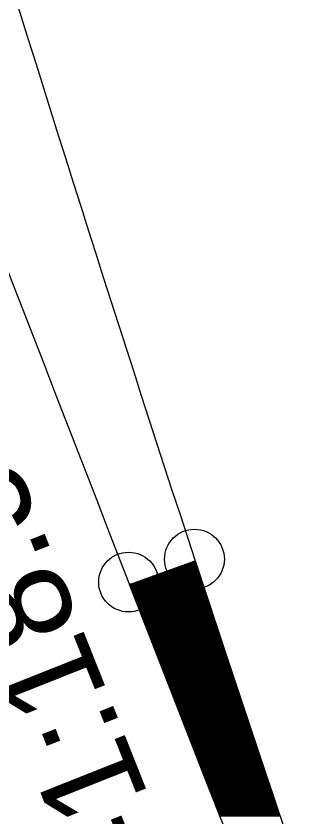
# Model space of a CAD drawing. Extents: x 149855 to 151460, y 6580726 to 6583068.
# Drawn here: x 151017.81 to 151025.23, y 6581493.39 to 6581513.46 of the extents above; entities that cross this region are included whole.
import ezdxf

# ---------------------------------------------------------------- set-up
doc = ezdxf.new("R2010")
doc.units = 0
for name, color, linetype in [('Spårmitt L', 7, 'Continuous'), ('Tp bef behålls P', 7, 'Continuous'), ('Växel L', 7, 'Continuous'), ('Växeltyp T', 7, 'Continuous')]:
    doc.layers.add(name, color=color, linetype=linetype)

msp = doc.modelspace()

# ---------------------------------------------------------------- linework, layer by layer
at = {"layer": 'Spårmitt L'}
for centre, radius, start, end in [((151635.017, 6581718.794), 629.5, 193.95613, 203.78913), ((154375.793, 6582804.201), 3600, 200.503925, 201.252844), ((151878.454, 6581780.709), 901.064, 195.629249, 198.165417), ((154379.055, 6582805.47), 3603.5, 201.252844, 202.283548)]:
    msp.add_arc(centre, radius, start, end, dxfattribs=at)
at = {"layer": 'Tp bef behålls P'}
for centre in [(151022.281, 6581499.835), (151020.63, 6581499.258)]:
    msp.add_circle(centre, 0.75, dxfattribs=at)
at = {"layer": 'Växel L'}
for p, q in [((151022.188, 6581499.752), (151022.312, 6581499.752)), ((151022.244, 6581499.772), (151022.306, 6581499.772)), ((151021.63, 6581499.552), (151022.378, 6581499.552)), ((151021.686, 6581499.572), (151022.372, 6581499.572)), ((151021.741, 6581499.592), (151022.365, 6581499.592)), ((151021.797, 6581499.612), (151022.358, 6581499.612)), ((151021.853, 6581499.632), (151022.352, 6581499.632)), ((151021.909, 6581499.652), (151022.345, 6581499.652)), ((151021.965, 6581499.672), (151022.339, 6581499.672)), ((151022.021, 6581499.692), (151022.332, 6581499.692)), ((151022.076, 6581499.712), (151022.325, 6581499.712)), ((151022.132, 6581499.732), (151022.319, 6581499.732)), ((151021.071, 6581499.352), (151022.444, 6581499.352)), ((151021.127, 6581499.372), (151022.437, 6581499.372)), ((151021.183, 6581499.392), (151022.431, 6581499.392)), ((151021.239, 6581499.412), (151022.424, 6581499.412)), ((151021.295, 6581499.432), (151022.418, 6581499.432)), ((151021.351, 6581499.452), (151022.411, 6581499.452)), ((151021.406, 6581499.472), (151022.404, 6581499.472)), ((151021.462, 6581499.492), (151022.398, 6581499.492)), ((151021.518, 6581499.512), (151022.391, 6581499.512)), ((151021.574, 6581499.532), (151022.385, 6581499.532)), ((151020.655, 6581499.192), (151022.497, 6581499.192)), ((151020.663, 6581499.172), (151022.503, 6581499.172)), ((151020.671, 6581499.152), (151022.51, 6581499.152)), ((151020.681, 6581499.212), (151022.49, 6581499.212)), ((151020.736, 6581499.232), (151022.484, 6581499.232)), ((151020.792, 6581499.252), (151022.477, 6581499.252)), ((151020.848, 6581499.272), (151022.47, 6581499.272)), ((151020.904, 6581499.292), (151022.464, 6581499.292)), ((151020.96, 6581499.312), (151022.457, 6581499.312)), ((151021.016, 6581499.332), (151022.451, 6581499.332)), ((151020.679, 6581499.132), (151022.517, 6581499.132)), ((151020.687, 6581499.112), (151022.523, 6581499.112)), ((151020.694, 6581499.092), (151022.53, 6581499.092)), ((151020.702, 6581499.072), (151022.536, 6581499.072)), ((151020.71, 6581499.052), (151022.543, 6581499.052)), ((151020.718, 6581499.032), (151022.55, 6581499.032)), ((151020.726, 6581499.012), (151022.556, 6581499.012)), ((151020.733, 6581498.992), (151022.563, 6581498.992)), ((151020.741, 6581498.972), (151022.569, 6581498.972)), ((151020.749, 6581498.952), (151022.576, 6581498.952)), ((151020.757, 6581498.932), (151022.582, 6581498.932)), ((151020.765, 6581498.912), (151022.589, 6581498.912)), ((151020.772, 6581498.892), (151022.596, 6581498.892)), ((151020.78, 6581498.872), (151022.602, 6581498.872)), ((151020.788, 6581498.852), (151022.609, 6581498.852)), ((151020.796, 6581498.832), (151022.615, 6581498.832)), ((151020.804, 6581498.812), (151022.622, 6581498.812)), ((151020.811, 6581498.792), (151022.629, 6581498.792)), ((151020.819, 6581498.772), (151022.635, 6581498.772)), ((151020.827, 6581498.752), (151022.642, 6581498.752)), ((151020.835, 6581498.732), (151022.648, 6581498.732)), ((151020.843, 6581498.712), (151022.655, 6581498.712)), ((151020.85, 6581498.692), (151022.662, 6581498.692)), ((151020.858, 6581498.672), (151022.668, 6581498.672)), ((151020.866, 6581498.652), (151022.675, 6581498.652)), ((151020.874, 6581498.632), (151022.681, 6581498.632)), ((151020.882, 6581498.612), (151022.688, 6581498.612)), ((151020.889, 6581498.592), (151022.695, 6581498.592)), ((151020.897, 6581498.572), (151022.701, 6581498.572)), ((151020.905, 6581498.552), (151022.708, 6581498.552)), ((151020.913, 6581498.532), (151022.714, 6581498.532)), ((151020.92, 6581498.512), (151022.721, 6581498.512)), ((151020.928, 6581498.492), (151022.728, 6581498.492)), ((151020.936, 6581498.472), (151022.734, 6581498.472)), ((151020.944, 6581498.452), (151022.741, 6581498.452)), ((151020.952, 6581498.432), (151022.747, 6581498.432)), ((151020.959, 6581498.412), (151022.754, 6581498.412)), ((151020.967, 6581498.392), (151022.761, 6581498.392)), ((151020.975, 6581498.372), (151022.767, 6581498.372)), ((151020.983, 6581498.352), (151022.774, 6581498.352)), ((151020.991, 6581498.332), (151022.78, 6581498.332)), ((151020.998, 6581498.312), (151022.787, 6581498.312)), ((151021.006, 6581498.292), (151022.793, 6581498.292)), ((151021.014, 6581498.272), (151022.8, 6581498.272)), ((151021.022, 6581498.252), (151022.807, 6581498.252)), ((151021.03, 6581498.232), (151022.813, 6581498.232)), ((151021.037, 6581498.212), (151022.82, 6581498.212)), ((151021.045, 6581498.192), (151022.826, 6581498.192)), ((151021.053, 6581498.172), (151022.833, 6581498.172)), ((151021.061, 6581498.152), (151022.84, 6581498.152)), ((151021.069, 6581498.132), (151022.846, 6581498.132)), ((151021.076, 6581498.112), (151022.853, 6581498.112)), ((151021.084, 6581498.092), (151022.859, 6581498.092)), ((151021.092, 6581498.072), (151022.866, 6581498.072)), ((151021.1, 6581498.052), (151022.873, 6581498.052)), ((151021.108, 6581498.032), (151022.879, 6581498.032)), ((151021.115, 6581498.012), (151022.886, 6581498.012)), ((151021.123, 6581497.992), (151022.892, 6581497.992)), ((151021.131, 6581497.972), (151022.899, 6581497.972)), ((151021.139, 6581497.952), (151022.906, 6581497.952)), ((151021.147, 6581497.932), (151022.912, 6581497.932)), ((151021.154, 6581497.912), (151022.919, 6581497.912)), ((151021.162, 6581497.892), (151022.925, 6581497.892)), ((151021.17, 6581497.872), (151022.932, 6581497.872)), ((151021.178, 6581497.852), (151022.939, 6581497.852)), ((151021.186, 6581497.832), (151022.945, 6581497.832)), ((151021.193, 6581497.812), (151022.952, 6581497.812)), ((151021.201, 6581497.792), (151022.958, 6581497.792)), ((151021.209, 6581497.772), (151022.965, 6581497.772)), ((151021.217, 6581497.752), (151022.972, 6581497.752)), ((151021.225, 6581497.732), (151022.978, 6581497.732)), ((151021.232, 6581497.712), (151022.985, 6581497.712)), ((151021.24, 6581497.692), (151022.991, 6581497.692)), ((151021.248, 6581497.672), (151022.998, 6581497.672)), ((151021.256, 6581497.652), (151023.004, 6581497.652)), ((151021.264, 6581497.632), (151023.011, 6581497.632)), ((151021.271, 6581497.612), (151023.018, 6581497.612)), ((151021.279, 6581497.592), (151023.024, 6581497.592)), ((151021.287, 6581497.572), (151023.031, 6581497.572)), ((151021.295, 6581497.552), (151023.037, 6581497.552)), ((151021.302, 6581497.532), (151023.044, 6581497.532)), ((151021.31, 6581497.512), (151023.051, 6581497.512)), ((151021.318, 6581497.492), (151023.057, 6581497.492)), ((151021.326, 6581497.472), (151023.064, 6581497.472)), ((151021.334, 6581497.452), (151023.07, 6581497.452)), ((151021.341, 6581497.432), (151023.077, 6581497.432)), ((151021.349, 6581497.412), (151023.084, 6581497.412)), ((151021.357, 6581497.392), (151023.09, 6581497.392)), ((151021.365, 6581497.372), (151023.097, 6581497.372)), ((151021.373, 6581497.352), (151023.103, 6581497.352)), ((151021.38, 6581497.332), (151023.11, 6581497.332)), ((151021.388, 6581497.312), (151023.117, 6581497.312)), ((151021.396, 6581497.292), (151023.123, 6581497.292)), ((151021.404, 6581497.272), (151023.13, 6581497.272)), ((151021.412, 6581497.252), (151023.136, 6581497.252)), ((151021.419, 6581497.232), (151023.143, 6581497.232)), ((151021.427, 6581497.212), (151023.15, 6581497.212)), ((151021.435, 6581497.192), (151023.156, 6581497.192)), ((151021.443, 6581497.172), (151023.163, 6581497.172)), ((151021.451, 6581497.152), (151023.17, 6581497.152)), ((151021.458, 6581497.132), (151023.176, 6581497.132)), ((151021.466, 6581497.112), (151023.183, 6581497.112)), ((151021.474, 6581497.092), (151023.19, 6581497.092)), ((151021.482, 6581497.072), (151023.196, 6581497.072)), ((151021.49, 6581497.052), (151023.203, 6581497.052)), ((151021.497, 6581497.032), (151023.21, 6581497.032)), ((151021.505, 6581497.012), (151023.216, 6581497.012)), ((151021.513, 6581496.992), (151023.223, 6581496.992)), ((151021.521, 6581496.972), (151023.23, 6581496.972)), ((151021.529, 6581496.952), (151023.236, 6581496.952)), ((151021.536, 6581496.932), (151023.243, 6581496.932)), ((151021.544, 6581496.912), (151023.249, 6581496.912)), ((151021.552, 6581496.892), (151023.256, 6581496.892)), ((151021.56, 6581496.872), (151023.263, 6581496.872)), ((151021.568, 6581496.852), (151023.269, 6581496.852)), ((151021.575, 6581496.832), (151023.276, 6581496.832)), ((151021.583, 6581496.812), (151023.283, 6581496.812)), ((151021.591, 6581496.792), (151023.289, 6581496.792)), ((151021.599, 6581496.772), (151023.296, 6581496.772)), ((151021.607, 6581496.752), (151023.303, 6581496.752)), ((151021.614, 6581496.732), (151023.309, 6581496.732)), ((151021.622, 6581496.712), (151023.316, 6581496.712)), ((151021.63, 6581496.692), (151023.323, 6581496.692)), ((151021.638, 6581496.672), (151023.329, 6581496.672)), ((151021.646, 6581496.652), (151023.336, 6581496.652)), ((151021.653, 6581496.632), (151023.343, 6581496.632)), ((151021.661, 6581496.612), (151023.349, 6581496.612)), ((151021.669, 6581496.592), (151023.356, 6581496.592)), ((151021.677, 6581496.572), (151023.363, 6581496.572)), ((151021.685, 6581496.552), (151023.369, 6581496.552)), ((151021.692, 6581496.532), (151023.376, 6581496.532)), ((151021.7, 6581496.512), (151023.383, 6581496.512)), ((151021.708, 6581496.492), (151023.389, 6581496.492)), ((151021.716, 6581496.472), (151023.396, 6581496.472)), ((151021.723, 6581496.452), (151023.403, 6581496.452)), ((151021.731, 6581496.432), (151023.409, 6581496.432)), ((151021.739, 6581496.412), (151023.416, 6581496.412)), ((151021.747, 6581496.392), (151023.423, 6581496.392)), ((151021.755, 6581496.372), (151023.429, 6581496.372)), ((151021.762, 6581496.352), (151023.436, 6581496.352)), ((151021.77, 6581496.332), (151023.443, 6581496.332)), ((151021.778, 6581496.312), (151023.449, 6581496.312)), ((151021.786, 6581496.292), (151023.456, 6581496.292)), ((151021.794, 6581496.272), (151023.463, 6581496.272)), ((151021.801, 6581496.252), (151023.469, 6581496.252)), ((151021.809, 6581496.232), (151023.476, 6581496.232)), ((151021.817, 6581496.212), (151023.483, 6581496.212)), ((151021.825, 6581496.192), (151023.489, 6581496.192)), ((151021.833, 6581496.172), (151023.496, 6581496.172)), ((151021.84, 6581496.152), (151023.503, 6581496.152)), ((151021.848, 6581496.132), (151023.509, 6581496.132)), ((151021.856, 6581496.112), (151023.516, 6581496.112)), ((151021.864, 6581496.092), (151023.523, 6581496.092)), ((151021.872, 6581496.072), (151023.529, 6581496.072)), ((151021.879, 6581496.052), (151023.536, 6581496.052)), ((151021.887, 6581496.032), (151023.543, 6581496.032)), ((151021.895, 6581496.012), (151023.549, 6581496.012)), ((151021.903, 6581495.992), (151023.556, 6581495.992)), ((151021.911, 6581495.972), (151023.563, 6581495.972)), ((151021.918, 6581495.952), (151023.569, 6581495.952)), ((151021.926, 6581495.932), (151023.576, 6581495.932)), ((151021.934, 6581495.912), (151023.582, 6581495.912)), ((151021.942, 6581495.892), (151023.589, 6581495.892)), ((151021.95, 6581495.872), (151023.596, 6581495.872)), ((151021.957, 6581495.852), (151023.602, 6581495.852)), ((151021.965, 6581495.832), (151023.609, 6581495.832)), ((151021.973, 6581495.812), (151023.616, 6581495.812)), ((151021.981, 6581495.792), (151023.622, 6581495.792)), ((151021.989, 6581495.772), (151023.629, 6581495.772)), ((151021.996, 6581495.752), (151023.636, 6581495.752)), ((151022.004, 6581495.732), (151023.642, 6581495.732)), ((151022.012, 6581495.712), (151023.649, 6581495.712)), ((151022.02, 6581495.692), (151023.656, 6581495.692)), ((151022.028, 6581495.672), (151023.662, 6581495.672)), ((151022.035, 6581495.652), (151023.669, 6581495.652)), ((151022.043, 6581495.632), (151023.676, 6581495.632)), ((151022.051, 6581495.612), (151023.682, 6581495.612)), ((151022.059, 6581495.592), (151023.689, 6581495.592)), ((151022.067, 6581495.572), (151023.696, 6581495.572)), ((151022.074, 6581495.552), (151023.702, 6581495.552)), ((151022.082, 6581495.532), (151023.709, 6581495.532)), ((151022.09, 6581495.512), (151023.716, 6581495.512)), ((151022.098, 6581495.492), (151023.722, 6581495.492)), ((151022.105, 6581495.472), (151023.729, 6581495.472)), ((151022.113, 6581495.452), (151023.736, 6581495.452)), ((151022.121, 6581495.432), (151023.742, 6581495.432)), ((151022.129, 6581495.412), (151023.749, 6581495.412)), ((151022.137, 6581495.392), (151023.756, 6581495.392)), ((151022.144, 6581495.372), (151023.762, 6581495.372)), ((151022.152, 6581495.352), (151023.769, 6581495.352)), ((151022.16, 6581495.332), (151023.776, 6581495.332)), ((151022.168, 6581495.312), (151023.782, 6581495.312)), ((151022.176, 6581495.292), (151023.789, 6581495.292)), ((151022.183, 6581495.272), (151023.796, 6581495.272)), ((151022.191, 6581495.252), (151023.802, 6581495.252)), ((151022.199, 6581495.232), (151023.809, 6581495.232)), ((151022.207, 6581495.212), (151023.816, 6581495.212)), ((151022.215, 6581495.192), (151023.822, 6581495.192)), ((151022.222, 6581495.172), (151023.829, 6581495.172)), ((151022.23, 6581495.152), (151023.836, 6581495.152)), ((151022.238, 6581495.132), (151023.842, 6581495.132)), ((151022.246, 6581495.112), (151023.849, 6581495.112)), ((151022.254, 6581495.092), (151023.856, 6581495.092)), ((151022.261, 6581495.072), (151023.862, 6581495.072)), ((151022.269, 6581495.052), (151023.869, 6581495.052)), ((151022.277, 6581495.032), (151023.876, 6581495.032)), ((151022.285, 6581495.012), (151023.882, 6581495.012)), ((151022.293, 6581494.992), (151023.889, 6581494.992)), ((151022.3, 6581494.972), (151023.896, 6581494.972)), ((151022.308, 6581494.952), (151023.902, 6581494.952)), ((151022.316, 6581494.932), (151023.909, 6581494.932)), ((151022.324, 6581494.912), (151023.915, 6581494.912)), ((151022.332, 6581494.892), (151023.922, 6581494.892)), ((151022.339, 6581494.872), (151023.929, 6581494.872)), ((151022.347, 6581494.852), (151023.935, 6581494.852)), ((151022.355, 6581494.832), (151023.942, 6581494.832)), ((151022.363, 6581494.812), (151023.949, 6581494.812)), ((151022.371, 6581494.792), (151023.955, 6581494.792)), ((151022.378, 6581494.772), (151023.962, 6581494.772)), ((151022.386, 6581494.752), (151023.969, 6581494.752)), ((151022.394, 6581494.732), (151023.975, 6581494.732)), ((151022.402, 6581494.712), (151023.982, 6581494.712)), ((151022.41, 6581494.692), (151023.989, 6581494.692)), ((151022.417, 6581494.672), (151023.995, 6581494.672)), ((151022.425, 6581494.652), (151024.002, 6581494.652)), ((151022.433, 6581494.632), (151024.009, 6581494.632)), ((151022.441, 6581494.612), (151024.016, 6581494.612)), ((151022.449, 6581494.592), (151024.022, 6581494.592)), ((151022.456, 6581494.572), (151024.029, 6581494.572)), ((151022.464, 6581494.552), (151024.036, 6581494.552)), ((151022.472, 6581494.532), (151024.043, 6581494.532)), ((151022.48, 6581494.512), (151024.049, 6581494.512)), ((151022.488, 6581494.492), (151024.056, 6581494.492)), ((151022.495, 6581494.472), (151024.063, 6581494.472)), ((151022.503, 6581494.452), (151024.069, 6581494.452)), ((151022.511, 6581494.432), (151024.076, 6581494.432)), ((151022.519, 6581494.412), (151024.083, 6581494.412)), ((151022.526, 6581494.392), (151024.09, 6581494.392)), ((151022.534, 6581494.372), (151024.096, 6581494.372)), ((151022.542, 6581494.352), (151024.103, 6581494.352)), ((151022.55, 6581494.332), (151024.11, 6581494.332)), ((151022.558, 6581494.312), (151024.116, 6581494.312)), ((151022.565, 6581494.292), (151024.123, 6581494.292)), ((151022.573, 6581494.272), (151024.13, 6581494.272)), ((151022.581, 6581494.252), (151024.137, 6581494.252)), ((151022.589, 6581494.232), (151024.143, 6581494.232)), ((151022.597, 6581494.212), (151024.15, 6581494.212)), ((151022.605, 6581494.192), (151024.157, 6581494.192)), ((151022.612, 6581494.172), (151024.164, 6581494.172)), ((151022.62, 6581494.152), (151024.17, 6581494.152)), ((151022.628, 6581494.132), (151024.177, 6581494.132)), ((151022.636, 6581494.112), (151024.184, 6581494.112)), ((151022.644, 6581494.092), (151024.19, 6581494.092)), ((151022.651, 6581494.072), (151024.197, 6581494.072)), ((151022.659, 6581494.052), (151024.204, 6581494.052)), ((151022.667, 6581494.032), (151024.211, 6581494.032)), ((151022.675, 6581494.012), (151024.217, 6581494.012)), ((151022.683, 6581493.992), (151024.224, 6581493.992)), ((151022.691, 6581493.972), (151024.231, 6581493.972)), ((151022.698, 6581493.952), (151024.238, 6581493.952)), ((151022.706, 6581493.932), (151024.244, 6581493.932)), ((151022.714, 6581493.912), (151024.251, 6581493.912)), ((151022.722, 6581493.892), (151024.258, 6581493.892)), ((151022.73, 6581493.872), (151024.264, 6581493.872)), ((151022.738, 6581493.852), (151024.271, 6581493.852)), ((151022.745, 6581493.832), (151024.278, 6581493.832)), ((151022.753, 6581493.812), (151024.285, 6581493.812)), ((151022.761, 6581493.792), (151024.291, 6581493.792)), ((151022.769, 6581493.772), (151024.298, 6581493.772)), ((151022.777, 6581493.752), (151024.305, 6581493.752)), ((151022.785, 6581493.732), (151024.312, 6581493.732)), ((151022.792, 6581493.712), (151024.318, 6581493.712)), ((151022.8, 6581493.692), (151024.325, 6581493.692)), ((151022.808, 6581493.672), (151024.332, 6581493.672)), ((151022.816, 6581493.652), (151024.338, 6581493.652)), ((151022.824, 6581493.632), (151024.345, 6581493.632)), ((151022.832, 6581493.612), (151024.352, 6581493.612)), ((151022.839, 6581493.592), (151024.359, 6581493.592)), ((151022.847, 6581493.572), (151024.365, 6581493.572)), ((151022.855, 6581493.552), (151024.372, 6581493.552)), ((151022.863, 6581493.532), (151024.379, 6581493.532)), ((151022.871, 6581493.512), (151024.386, 6581493.512)), ((151022.879, 6581493.492), (151024.392, 6581493.492)), ((151022.886, 6581493.472), (151024.399, 6581493.472)), ((151022.894, 6581493.452), (151024.406, 6581493.452)), ((151022.902, 6581493.432), (151024.412, 6581493.432)), ((151022.91, 6581493.412), (151024.419, 6581493.412)), ((151022.918, 6581493.392), (151024.426, 6581493.392))]:
    msp.add_line(p, q, dxfattribs=at)
msp.add_lwpolyline([(151024.561, 6581489.194), (151022.592, 6581494.224), (151020.652, 6581499.202), (151022.299, 6581499.792), (151023.144, 6581497.23), (151023.996, 6581494.671), (151024.856, 6581492.114)], dxfattribs=at)

# ---------------------------------------------------------------- texts
at = {"layer": 'Växeltyp T'}
msp.add_text('60E-1:18.5', height=2.5, rotation=111.6783, dxfattribs=at).set_placement((151023.769, 6581487.281))

doc.saveas('drawing.dxf')
